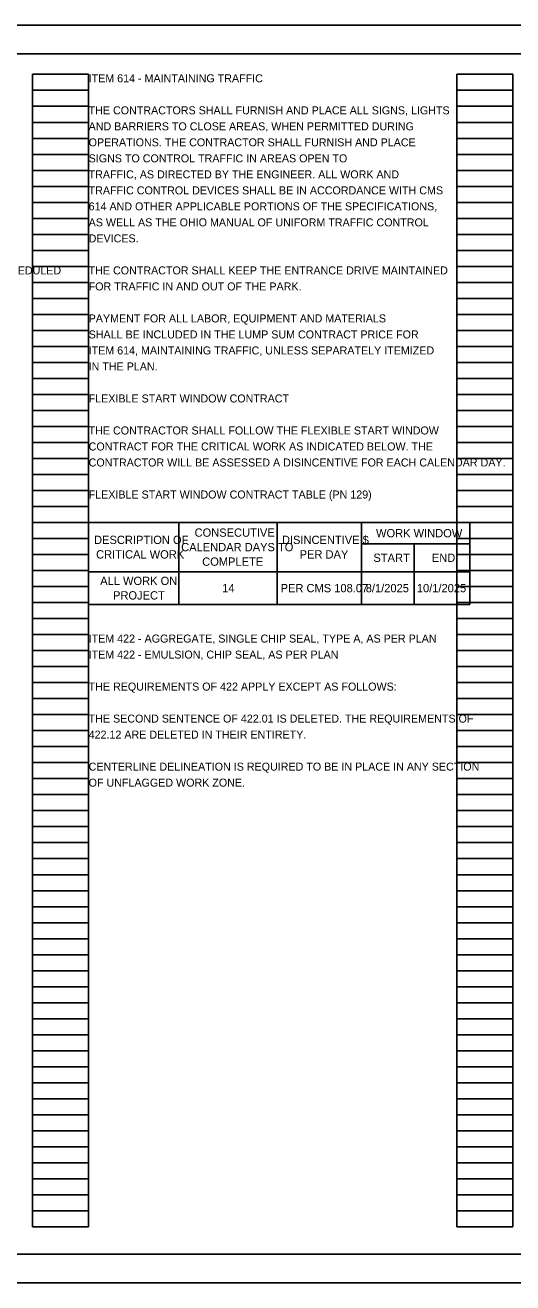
# Model space of a CAD drawing. Extents: x 0 to 46, y -1.1 to 22.
# Drawn here: x 16.13 to 24.66, y 0 to 22 of the extents above; entities that cross this region are included whole.
import ezdxf

# ---------------------------------------------------------------- set-up
doc = ezdxf.new("R2010")
doc.units = 0
for name, color, linetype in [('Default', 7, 'Continuous'), ('SH_Border', 7, 'Continuous'), ('SH_Cut_Line', 7, 'Continuous'), ('SH_Data', 7, 'Continuous'), ('SH_Text', 7, 'Continuous')]:
    doc.layers.add(name, color=color, linetype=linetype)

msp = doc.modelspace()

# ---------------------------------------------------------------- linework, layer by layer
at = {"layer": 'Default'}
for p, q in [((17.24, 13.3), (23.907, 13.3)), ((17.24, 13.3), (17.24, 11.866)), ((18.817, 13.3), (18.817, 11.866)), ((20.538, 13.3), (20.538, 11.866)), ((22.014, 13.3), (22.014, 11.866)), ((23.907, 13.3), (23.907, 11.866)), ((22.014, 12.927), (23.907, 12.927)), ((22.932, 12.927), (22.932, 11.866)), ((17.24, 12.44), (23.907, 12.44)), ((17.24, 11.866), (23.907, 11.866))]:
    msp.add_line(p, q, dxfattribs=at)
at = {"layer": 'SH_Border'}
msp.add_lwpolyline([(1.5, 21.5), (33.5, 21.5), (33.5, 0.5), (1.5, 0.5)], close=True, dxfattribs=at)
at = {"layer": 'SH_Cut_Line'}
msp.add_lwpolyline([(0, 0), (34, 0), (34, 22), (0, 22)], close=True, dxfattribs=at)
at = {"layer": 'SH_Data'}
for p, q in [((16.26, 0.98), (16.26, 21.14)), ((16.26, 21.14), (17.24, 21.14)), ((17.24, 0.98), (17.24, 21.14)), ((23.68, 0.98), (23.68, 21.14)), ((23.68, 21.14), (24.66, 21.14)), ((24.66, 0.98), (24.66, 21.14)), ((16.26, 20.86), (17.24, 20.86)), ((23.68, 20.86), (24.66, 20.86)), ((16.26, 20.58), (17.24, 20.58)), ((23.68, 20.58), (24.66, 20.58)), ((16.26, 20.3), (17.24, 20.3)), ((23.68, 20.3), (24.66, 20.3)), ((16.26, 20.02), (17.24, 20.02)), ((23.68, 20.02), (24.66, 20.02)), ((16.26, 19.74), (17.24, 19.74)), ((23.68, 19.74), (24.66, 19.74)), ((16.26, 19.46), (17.24, 19.46)), ((23.68, 19.46), (24.66, 19.46)), ((16.26, 19.18), (17.24, 19.18)), ((23.68, 19.18), (24.66, 19.18)), ((16.26, 18.9), (17.24, 18.9)), ((23.68, 18.9), (24.66, 18.9)), ((16.26, 18.62), (17.24, 18.62)), ((23.68, 18.62), (24.66, 18.62)), ((16.26, 18.34), (17.24, 18.34)), ((23.68, 18.34), (24.66, 18.34)), ((16.26, 18.06), (17.24, 18.06)), ((23.68, 18.06), (24.66, 18.06)), ((16.26, 17.78), (17.24, 17.78)), ((23.68, 17.78), (24.66, 17.78)), ((16.26, 17.5), (17.24, 17.5)), ((23.68, 17.5), (24.66, 17.5)), ((16.26, 17.22), (17.24, 17.22)), ((23.68, 17.22), (24.66, 17.22)), ((16.26, 16.94), (17.24, 16.94)), ((23.68, 16.94), (24.66, 16.94)), ((16.26, 16.66), (17.24, 16.66)), ((23.68, 16.66), (24.66, 16.66)), ((16.26, 16.38), (17.24, 16.38)), ((23.68, 16.38), (24.66, 16.38)), ((16.26, 16.1), (17.24, 16.1)), ((23.68, 16.1), (24.66, 16.1)), ((16.26, 15.82), (17.24, 15.82)), ((23.68, 15.82), (24.66, 15.82)), ((16.26, 15.54), (17.24, 15.54)), ((23.68, 15.54), (24.66, 15.54)), ((16.26, 15.26), (17.24, 15.26)), ((23.68, 15.26), (24.66, 15.26)), ((16.26, 14.98), (17.24, 14.98)), ((23.68, 14.98), (24.66, 14.98)), ((16.26, 14.7), (17.24, 14.7)), ((23.68, 14.7), (24.66, 14.7)), ((16.26, 14.42), (17.24, 14.42)), ((23.68, 14.42), (24.66, 14.42)), ((16.26, 14.14), (17.24, 14.14)), ((23.68, 14.14), (24.66, 14.14)), ((16.26, 13.86), (17.24, 13.86)), ((23.68, 13.86), (24.66, 13.86)), ((16.26, 13.58), (17.24, 13.58)), ((23.68, 13.58), (24.66, 13.58)), ((16.26, 13.3), (17.24, 13.3)), ((23.68, 13.3), (24.66, 13.3)), ((16.26, 13.02), (17.24, 13.02)), ((23.68, 13.02), (24.66, 13.02)), ((16.26, 12.74), (17.24, 12.74)), ((23.68, 12.74), (24.66, 12.74)), ((16.26, 12.46), (17.24, 12.46)), ((23.68, 12.46), (24.66, 12.46)), ((16.26, 12.18), (17.24, 12.18)), ((23.68, 12.18), (24.66, 12.18)), ((16.26, 11.9), (17.24, 11.9)), ((23.68, 11.9), (24.66, 11.9)), ((16.26, 11.62), (17.24, 11.62)), ((23.68, 11.62), (24.66, 11.62)), ((16.26, 11.34), (17.24, 11.34)), ((23.68, 11.34), (24.66, 11.34)), ((16.26, 11.06), (17.24, 11.06)), ((23.68, 11.06), (24.66, 11.06)), ((16.26, 10.78), (17.24, 10.78)), ((23.68, 10.78), (24.66, 10.78)), ((16.26, 10.5), (17.24, 10.5)), ((23.68, 10.5), (24.66, 10.5)), ((16.26, 10.22), (17.24, 10.22)), ((23.68, 10.22), (24.66, 10.22)), ((16.26, 9.94), (17.24, 9.94)), ((23.68, 9.94), (24.66, 9.94)), ((16.26, 9.66), (17.24, 9.66)), ((23.68, 9.66), (24.66, 9.66)), ((16.26, 9.38), (17.24, 9.38)), ((23.68, 9.38), (24.66, 9.38)), ((16.26, 9.1), (17.24, 9.1)), ((23.68, 9.1), (24.66, 9.1)), ((16.26, 8.82), (17.24, 8.82)), ((23.68, 8.82), (24.66, 8.82)), ((16.26, 8.54), (17.24, 8.54)), ((23.68, 8.54), (24.66, 8.54)), ((16.26, 8.26), (17.24, 8.26)), ((23.68, 8.26), (24.66, 8.26)), ((16.26, 7.98), (17.24, 7.98)), ((23.68, 7.98), (24.66, 7.98)), ((16.26, 7.7), (17.24, 7.7)), ((23.68, 7.7), (24.66, 7.7)), ((16.26, 7.42), (17.24, 7.42)), ((23.68, 7.42), (24.66, 7.42)), ((16.26, 7.14), (17.24, 7.14)), ((23.68, 7.14), (24.66, 7.14)), ((16.26, 6.86), (17.24, 6.86)), ((23.68, 6.86), (24.66, 6.86)), ((16.26, 6.58), (17.24, 6.58)), ((23.68, 6.58), (24.66, 6.58)), ((16.26, 6.3), (17.24, 6.3)), ((23.68, 6.3), (24.66, 6.3)), ((16.26, 6.02), (17.24, 6.02)), ((23.68, 6.02), (24.66, 6.02)), ((16.26, 5.74), (17.24, 5.74)), ((23.68, 5.74), (24.66, 5.74)), ((16.26, 5.46), (17.24, 5.46)), ((23.68, 5.46), (24.66, 5.46)), ((16.26, 5.18), (17.24, 5.18)), ((23.68, 5.18), (24.66, 5.18)), ((16.26, 4.9), (17.24, 4.9)), ((23.68, 4.9), (24.66, 4.9)), ((16.26, 4.62), (17.24, 4.62)), ((23.68, 4.62), (24.66, 4.62)), ((16.26, 4.34), (17.24, 4.34)), ((23.68, 4.34), (24.66, 4.34)), ((16.26, 4.06), (17.24, 4.06)), ((23.68, 4.06), (24.66, 4.06)), ((16.26, 3.78), (17.24, 3.78)), ((23.68, 3.78), (24.66, 3.78)), ((16.26, 3.5), (17.24, 3.5)), ((23.68, 3.5), (24.66, 3.5)), ((16.26, 3.22), (17.24, 3.22)), ((23.68, 3.22), (24.66, 3.22)), ((16.26, 2.94), (17.24, 2.94)), ((23.68, 2.94), (24.66, 2.94)), ((16.26, 2.66), (17.24, 2.66)), ((23.68, 2.66), (24.66, 2.66)), ((16.26, 2.38), (17.24, 2.38)), ((23.68, 2.38), (24.66, 2.38)), ((16.26, 2.1), (17.24, 2.1)), ((23.68, 2.1), (24.66, 2.1)), ((16.26, 1.82), (17.24, 1.82)), ((23.68, 1.82), (24.66, 1.82)), ((16.26, 1.54), (17.24, 1.54)), ((23.68, 1.54), (24.66, 1.54)), ((16.26, 1.26), (17.24, 1.26)), ((23.68, 1.26), (24.66, 1.26)), ((16.26, 0.98), (17.24, 0.98)), ((23.68, 0.98), (24.66, 0.98))]:
    msp.add_line(p, q, dxfattribs=at)

# ---------------------------------------------------------------- texts
at = {"layer": 'Default'}
for s, p in [('DESCRIPTION OF ', (17.335, 12.924)), ('CONSECUTIVE ', (19.093, 13.051)), ('DISINCENTIVE $ ', (20.621, 12.924)), ('WORK WINDOW', (22.267, 13.041)), ('CRITICAL WORK', (17.37, 12.67)), ('CALENDAR DAYS TO ', (18.859, 12.797)), ('PER DAY', (20.931, 12.67)), ('COMPLETE', (19.226, 12.543)), ('START', (22.221, 12.611)), ('END', (23.244, 12.611)), ('ALL WORK ON ', (17.442, 12.207)), ('PROJECT', (17.667, 11.953)), ('14', (19.576, 12.08)), ('PER CMS 108.07', (20.598, 12.08)), ('8/1/2025', (22.087, 12.08)), ('10/1/2025', (22.981, 12.08))]:
    msp.add_text(s, height=0.1451, dxfattribs=at).set_placement(p)
at = {"layer": 'SH_Text'}
for s, p in [('ITEM 614 - MAINTAINING TRAFFIC', (17.24, 21)), ('THE CONTRACTORS SHALL FURNISH AND PLACE ALL SIGNS, LIGHTS', (17.24, 20.44)), ('AND BARRIERS TO CLOSE AREAS, WHEN PERMITTED DURING', (17.24, 20.16)), ('OPERATIONS. THE CONTRACTOR SHALL FURNISH AND PLACE', (17.24, 19.88)), ('SIGNS TO CONTROL TRAFFIC IN AREAS OPEN TO', (17.24, 19.6)), ('TRAFFIC, AS DIRECTED BY THE ENGINEER. ALL WORK AND ', (17.24, 19.32)), ('TRAFFIC CONTROL DEVICES SHALL BE IN ACCORDANCE WITH CMS', (17.24, 19.04)), ('614 AND OTHER APPLICABLE PORTIONS OF THE SPECIFICATIONS, ', (17.24, 18.76)), ('AS WELL AS THE OHIO MANUAL OF UNIFORM TRAFFIC CONTROL', (17.24, 18.48)), ('DEVICES. ', (17.24, 18.2)), ('SCHEDULED EVENT. THE DATES OF SPECIAL EVENTS WILL BE SCHEDULED', (9.82, 17.64)), ('THE CONTRACTOR SHALL KEEP THE ENTRANCE DRIVE MAINTAINED', (17.24, 17.64)), ('FOR TRAFFIC IN AND OUT OF THE PARK.', (17.24, 17.36)), ('PAYMENT FOR ALL LABOR, EQUIPMENT AND MATERIALS', (17.24, 16.8)), ('SHALL BE INCLUDED IN THE LUMP SUM CONTRACT PRICE FOR', (17.24, 16.52)), ('ITEM 614, MAINTAINING TRAFFIC, UNLESS SEPARATELY ITEMIZED', (17.24, 16.24)), ('IN THE PLAN.', (17.24, 15.96)), ('FLEXIBLE START WINDOW CONTRACT', (17.24, 15.4)), ('THE CONTRACTOR SHALL FOLLOW THE FLEXIBLE START WINDOW ', (17.24, 14.84)), ('CONTRACT FOR THE CRITICAL WORK AS INDICATED BELOW. THE ', (17.24, 14.56)), ('CONTRACTOR WILL BE ASSESSED A DISINCENTIVE FOR EACH CALENDAR DAY.', (17.24, 14.28)), ('FLEXIBLE START WINDOW CONTRACT TABLE (PN 129)', (17.24, 13.72)), ('ITEM 422 - AGGREGATE, SINGLE CHIP SEAL, TYPE A, AS PER PLAN', (17.24, 11.2)), ('ITEM 422 - EMULSION, CHIP SEAL, AS PER PLAN', (17.24, 10.92)), ('THE REQUIREMENTS OF 422 APPLY EXCEPT AS FOLLOWS:', (17.24, 10.36)), ('THE SECOND SENTENCE OF 422.01 IS DELETED. THE REQUIREMENTS OF ', (17.24, 9.8)), ('422.12 ARE DELETED IN THEIR ENTIRETY.', (17.24, 9.52)), ('CENTERLINE DELINEATION IS REQUIRED TO BE IN PLACE IN ANY SECTION ', (17.24, 8.96)), ('OF UNFLAGGED WORK ZONE.', (17.24, 8.68))]:
    msp.add_text(s, height=0.14, dxfattribs=at).set_placement(p)

doc.saveas('drawing.dxf')
